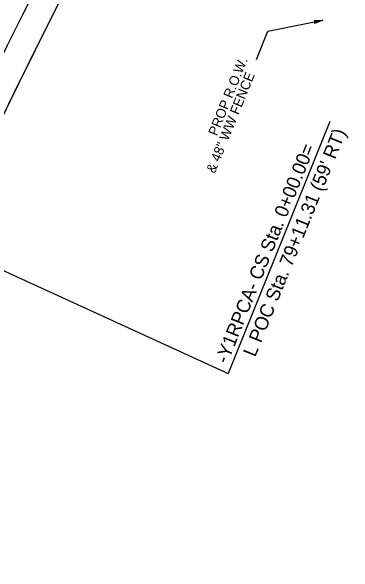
# Model space of a CAD drawing. Extents: x 2389694 to 2405615, y 546931 to 573532.
# Drawn here: x 2395658.7 to 2395835.1, y 556729.7 to 557018.8 of the extents above; entities that cross this region are included whole.
import ezdxf

# ---------------------------------------------------------------- set-up
doc = ezdxf.new("R2010")
doc.units = 0
for name, color, linetype in [('Old_Level_22', 7, 'Continuous'), ('Prop DSN Text', 7, 'Continuous'), ('Prop EOT', 7, 'Continuous'), ('Prop Guardrail', 7, 'Continuous'), ('Prop Horizontal Alignment', 7, 'Continuous'), ('Prop Horizontal Alignment Curve and Spiral Data', 7, 'Continuous'), ('Prop Lane Lines', 7, 'Continuous'), ('Prop SBG', 7, 'Continuous')]:
    doc.layers.add(name, color=color, linetype=linetype)

msp = doc.modelspace()

# ---------------------------------------------------------------- linework, layer by layer
at = {"layer": 'Prop DSN Text'}
for p, q in [((2395790.95, 557008.57), (2395819.28, 557014.22)), ((2395785.07, 556994.02), (2395790.95, 557008.57))]:
    msp.add_line(p, q, dxfattribs=at)
msp.add_lwpolyline([(2395814.71, 557014.12), (2395819.28, 557014.22), (2395814.99, 557012.57), (2395815.4, 557013.47)], close=True, dxfattribs=at)
at = {"layer": 'Prop EOT'}
for centre, radius, start, end in [((2398729.82, 555480.32), 3559, 136.54853, 163.17888), ((2398729.82, 555480.32), 3523, 136.54853, 169.40696), ((2398729.82, 555480.32), 3453, 136.54853, 155.44499), ((2398729.82, 555480.32), 3429, 136.54853, 155.44499), ((2398729.83, 555480.34), 3415, 150.73536, 155.44499)]:
    msp.add_arc(centre, radius, start, end, dxfattribs=at)
at = {"layer": 'Prop Guardrail'}
msp.add_arc((2398729.82, 555480.32), 3415, 149.9922, 155.44499, dxfattribs=at)
at = {"layer": 'Prop Horizontal Alignment'}
msp.add_arc((2398729.82, 555480.32), 3500, 136.54853, 177.15578, dxfattribs=at)
at = {"layer": 'Prop Horizontal Alignment Curve and Spiral Data'}
for p in [(2395822.84, 556962.05), (2395601.38, 556909.66)]:
    msp.add_line(p, (2395770.46, 556832.41), dxfattribs=at)
at = {"layer": 'Prop Lane Lines'}
for radius, end in [(3547, 169.40696), (3535, 169.40696), (3441, 155.44499)]:
    msp.add_arc((2398729.82, 555480.32), radius, 136.54853, end, dxfattribs=at)
at = {"layer": 'Prop SBG'}
msp.add_arc((2398729.82, 555480.32), 3415, 149.9922, 155.44499, dxfattribs=at)

# ---------------------------------------------------------------- texts
at = {"layer": 'Old_Level_22'}
for s, p in [("L POC Sta. 79+11.31 (59' RT)", (2395784.35, 556840.46)), ('-Y1RPCA- CS Sta. 0+00.00=', (2395769.99, 556836.96))]:
    msp.add_text(s, height=7, rotation=67.9866, dxfattribs=at).set_placement(p)
at = {"layer": 'Prop DSN Text'}
for s, p in [('PROP R.O.W.', (2395764.63, 556954.33)), ('& 48" WW FENCE', (2395763.6, 556935.1))]:
    msp.add_text(s, height=5, rotation=68, dxfattribs=at).set_placement(p)

doc.saveas('drawing.dxf')
